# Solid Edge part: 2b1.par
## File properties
Author: edge
Template: jis part.par
Last saved by: edge
Revision: 16
Application: Solid Edge
文書内容のタイプ: 0
Accuracy: 0.990
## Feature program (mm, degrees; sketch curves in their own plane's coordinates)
sketch for "unnamed Protrusion 1" plane through (0, 0, 0) normal (1, 0, 0) x-axis (0, 1, 0)
  line (-70, 0) -> (70, 0)
  line (70, 0) -> (70, 40)
  line (70, 40) -> (-70, 40)
  line (-70, 40) -> (-70, 0)
  dimension (linear) = 70
  dimension (linear) = 70
extrude "unnamed Protrusion 1" add finite 40 symmetric
sketch for "unnamed Cutout 1" plane through (0, 0, 0) normal (1, 0, 0) x-axis (0, 1, 0)
  circle centre (0, -2) radius 20
extrude "unnamed Cutout 1" cut through
thinwall "Thinwall_1"  Thickness = 2 mm
sketch for "unnamed Cutout 2" #1 plane through (0, 0, 0) normal (0, 0, 1) x-axis (1, 0, 0)
  circle centre (0, 50) radius 5
sketch for "unnamed Cutout 2" #2 plane through (0, 0, 0) normal (0, 0, 1) x-axis (1, 0, 0)
  circle centre (0, -50) radius 5
extrude "unnamed Cutout 2" cut through along +normal
fillet "Round_2" radius 10
fillet "Round_3" radius 10
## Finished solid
Body 1: solid body, 16 faces, 40 edges, 24 vertices.
  Faces by surface: cylinder 8, plane 8
  Edges by curve: line 24, circle 16
Bounding box of the edges (mm): 40.000 x 140.000 x 20.000, from (-20, -70, 0) to (20, 70, 20).
Cylindrical faces by radius (mm): R5 x2, R10 x4, R20 x1, R22 x1
Planar faces by outward normal: +x 1, +y 1, +z 2, -x 1, -y 1, -z 2
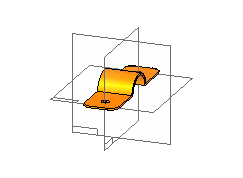
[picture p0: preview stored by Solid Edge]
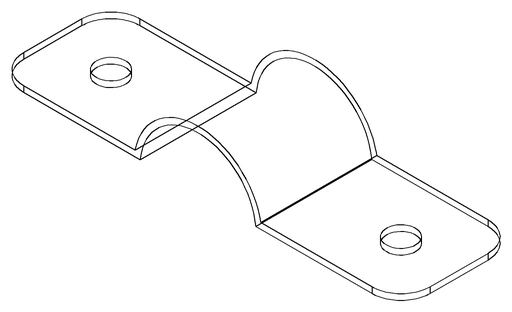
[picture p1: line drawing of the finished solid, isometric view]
